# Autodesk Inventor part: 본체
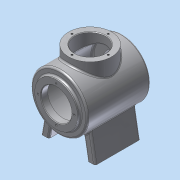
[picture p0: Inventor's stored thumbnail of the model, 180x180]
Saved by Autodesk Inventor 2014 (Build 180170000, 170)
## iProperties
Created: 2015-01
Part Number: 본체
Material: 알루미늄 6061
Document SubType Name: Modeling
Designer: user
Density: 2.71 g/cm^3
Appearance: 알루미늄 - 평지
Mass: 1021.13 g
Surface Area: 1060.37 cm^2
Volume: 376.8 cm^3
Author: user
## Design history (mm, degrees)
sketch "스케치1"
  geometry: L1 (0, 0)-(122, 0); L2 (0, 27)-(12, 27); L3 (12, 45)-(109, 45); L4 (12, 27)-(12, 45); L5 (109, 27)-(122, 27); L6 (109, 45)-(109, 27); L7 (0, 38)-(5, 38); L8 (0, 27)-(0, 38); L9 (5, 50)-(117, 50); L10 (5, 38)-(5, 50); L11 (117, 38)-(122, 38); L12 (117, 50)-(117, 38); L13 (122, 38)-(122, 27)
  constraints: 26 end point, 8 perpendicular, 3 vertical alignment, 2 parallel, 1 horizontal
  dimensions: "d0" = 122 distance of L1.start L1.end; "d3" = 12 distance of L2.start L2.end; "d4" = 27 distance between parallel lines of L1 L2; "d5" = 97 distance of L3.start L3.end; "d6" = 45 distance between parallel lines of L1 L3; "d7" = 13 distance of L5.start L5.end; "d8" = 27 distance between parallel lines of L1 L5; "d9" = 5 distance of L7.start L7.end; "d10" = 38 distance between parallel lines of L1 L7; "d11" = 112 distance of L9.start L9.end; "d12" = 50 distance between parallel lines of L1 L9; "d13" = 5 distance of L11.start L11.end; "d14" = 38 distance between parallel lines of L1 L11
revolve "회전1" sketch "스케치1" stored, may be unused: angle "d15" = 90 deg
node "작업 평면1"
sketch "스케치2"
  geometry: L1 (-80, -48)-(-80, -34); L2 (-80, -34)-(-41.901, -27.282); L3 (-41.901, 27.282)-(-80, 34); L4 (-80, 34)-(-80, 48); L5 (-80, 48)-(-30.865, 39.336); L6 (-30.865, -39.336)-(-80, -48); C1 r 45 at (0, 0) reference; C2 r 38 at (0, 0) reference; A1 r 50 centre (0, 0) between (-30.865, -39.336) and (-30.865, 39.336) reference; A2 r 50 centre (0, 0) between (-41.901, -27.282) and (-30.865, -39.336); A3 r 50 centre (0, 0) between (-30.865, 39.336) and (-41.901, 27.282); 1 further point
  constraints: 12 end point, 8 point on circle, 2 centre point, 2 collinear, 2 concentric, 2 parallel, 1 vertical
  dimensions: "d17" = 14 distance of L1.start L1.end; "d18" = 14 distance of L3.end L4.end; "d19" = 100 deg angle of L4 L3; "d20" = 100 deg angle of L2 L1; "d21" = 96 distance of L4.end L1.start; "d22" = 80 distance from line of L1 point (0, 0); "d23" = 48 vertical distance of L1.start point (0, 0)
extrude "돌출1" join sketch "스케치2" distance "d24" = 80; taper "d25" = 0 deg
node "작업 평면3"
sketch "스케치3"
  geometry: L1 (101, -30.865)-(21, -30.865) reference; L2 (21, -30.865)-(21, -41.901) reference; L3 (21, -41.901)-(101, -41.901) reference; L4 (101, -41.901)-(101, -30.865) reference; L5 (21, -30.865)-(101, -30.865) reference; L6 (101, -30.865)-(101, -41.901) reference; L7 (101, -41.901)-(21, -41.901) reference; L8 (21, -41.901)-(21, -30.865) reference; L9 (5, 50)-(5, -50) reference; L10 (117, 50)-(117, -50) reference; L11 (88, 6)-(34, 6); L12 (34, 6)-(34, -6); L13 (34, -6)-(88, -6); L14 (88, -6)-(88, 6); L15 (21, -80)-(101, -80) reference; 3 further points
  constraints: 8 end point, 2 midpoint, 2 parallel, 1 horizontal, 1 perpendicular, 1 vertical alignment
  dimensions: "d28" = 54 distance of L11.start L11.end; "d29" = 12 distance of L13.end L11.start; "d30" = 74 distance from line of L13.end L15
extrude "돌출2" join sketch "스케치3" distance "d31" = 2; taper "d33" = 0 deg; dims "d32" = 2, "d34" = 0
sketch "스케치4"
  geometry: L1 (-34, 6)-(-88, 6) reference; L2 (-88, 6)-(-88, -6) reference; L3 (-88, -6)-(-34, -6) reference; L4 (-34, -6)-(-34, 6) reference; 4 further points
  constraints: 2 midpoint, 1 horizontal alignment, 1 vertical alignment, 1 other
feature "엠보싱1" sketch "스케치4" dims "d0" = 122, "d3" = 12, "d4" = 27, "d5" = 97, "d6" = 45, "d7" = 13, "d8" = 27, "d9" = 5, "d10" = 38, "d11" = 112, "d12" = 50, "d13" = 5, "d14" = 38, "d17" = 14, "d18" = 14, "d19" = 100 deg, "d20" = 100 deg, "d21" = 96, "d22" = 80, "d23" = 48, "d35" = 0.5, "d36" = 0
node "작업 평면4"
sketch "스케치5"
  geometry: L1 (-122, -38)-(-122, 38) reference; L2 (0, -38)-(0, 38) reference; C1 r 38 at (-60, 0); 1 further point
  constraints: 1 centre point, 1 horizontal alignment
  dimensions: "d38" = 38 radius of C1; "d39" = 60 distance of point (0, 0) C1.centre
extrude "돌출3" join sketch "스케치5" stored distance "d40" = 2; taper "d41" = 0 deg
sketch "스케치6"
  geometry: C1 r 38 at (0, 0) reference; C2 r 27 at (0, 0); 1 further point
  constraints: 1 centre point, 1 coincident
  dimensions: "d42" = 27 radius of C2
extrude "돌출4" cut sketch "스케치6" stored distance "d43" = 2; taper "d44" = 0 deg
sketch "스케치7"
  geometry: 2 further points
  constraints: 1 vertical alignment
  dimensions: "d45" = 32 distance of point (0, 0) point (0, 32)
hole "구멍1" sketch "스케치7" at (0, 32) diameter "d46" = 3.242; stored, may be unused: countersink angle "d50" = 90 deg, drill point angle "d52" = 118 deg; dims "d47" = 8, "d48" = 4, "d49" = 2, "d51" = 10
node "작업 평면5"
sketch "스케치8"
  geometry: L1 (-39, -34)-(41, -34) reference; C1 r 27 at (0, 0) reference; C2 r 38 at (0, 0) reference; 2 further points
  constraints: 1 vertical alignment
  dimensions: "d57" = 32 distance of C1.centre point (0, -32)
hole "구멍2" sketch "스케치8" at (0, -32) diameter "d58" = 3.242; stored, may be unused: countersink angle "d62" = 90 deg, drill point angle "d64" = 118 deg; dims "d59" = 8, "d60" = 4, "d61" = 2, "d63" = 10
fillet "모깎기1" dims "d68" = 3
fillet "모깎기2" dims "d69" = 3
fillet "모깎기3" dims "d70" = 3
fillet "모깎기4" dims "d71" = 3
fillet "모깎기5" dims "d72" = 3
chamfer "모따기1" distance "d73" = 1; stored, may be unused: second distance "d74" = 2, angle "d75" = 45 deg
chamfer "모따기2" distance "d76" = 1; stored, may be unused: second distance "d77" = 2, angle "d78" = 45 deg
chamfer "모따기3" distance "d79" = 1; stored, may be unused: second distance "d80" = 2, angle "d81" = 45 deg
node "솔리드1"
pattern_circular "원형 패턴1" dims angle "d54" = 360 deg
mirror "대칭1"
pattern_circular "원형 패턴2" dims angle "d66" = 360 deg
node "투영된 루프1"
node "투영된 루프2"
node "투영된 루프3"
node "투영된 루프4"
other parameters: "d16" = 21, "d37" = 62, "d56" = 61
